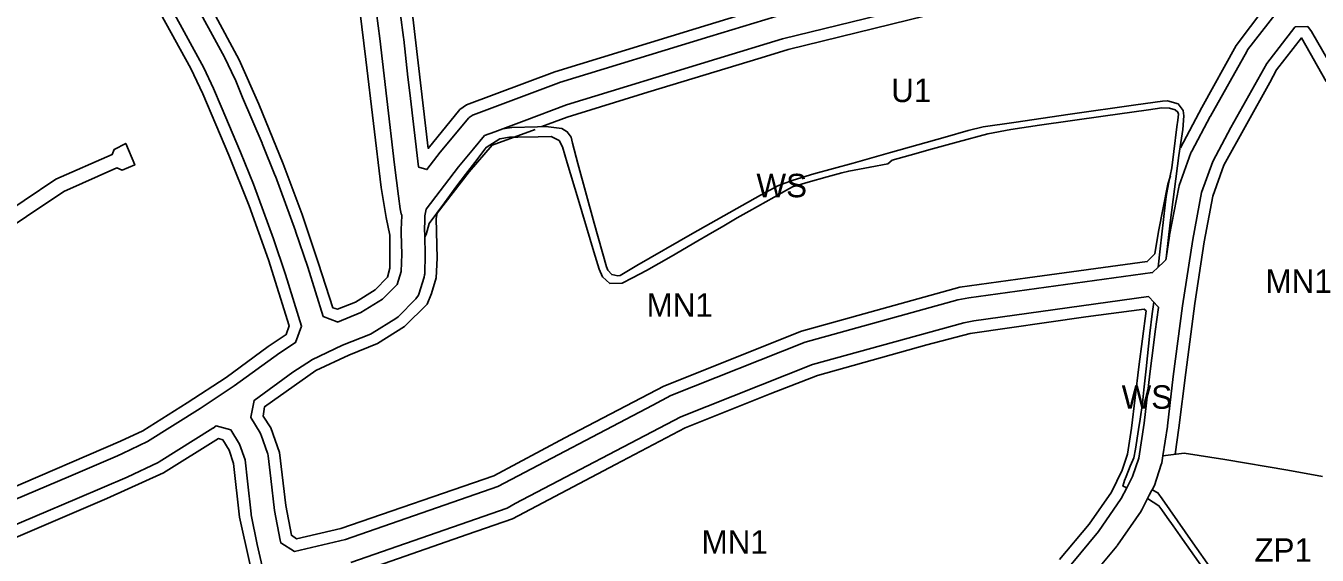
# Model space of a CAD drawing. Extents: x -284239 to -281592, y 34477 to 37267.
# Drawn here: x -283094 to -282544, y 35090 to 35315 of the extents above; entities that cross this region are included whole.
import ezdxf

# ---------------------------------------------------------------- set-up
doc = ezdxf.new("R2010")
doc.units = 0
for name, color, linetype in [('linie_rozgraniczajace', 7, 'Continuous'), ('linie_zabudowy_nieprzekraczalne', 7, 'Continuous'), ('oznaczenia_przeznaczen', 7, 'Continuous')]:
    doc.layers.add(name, color=color, linetype=linetype)

msp = doc.modelspace()

# ---------------------------------------------------------------- linework, layer by layer
at = {"layer": 'linie_rozgraniczajace'}
for points in [[(-283023.658, 35328.372), (-283009.305, 35301.979), (-283009.197, 35301.753), (-283009.173, 35301.719), (-283004.94, 35292.724), (-283004.917, 35292.623), (-283004.852, 35292.526), (-283001.616, 35284.8), (-282993.288, 35265.235), (-282993.278, 35265.188), (-282993.252, 35265.149), (-282987.696, 35251.39), (-282987.679, 35251.301), (-282987.636, 35251.234), (-282979.103, 35227.885), (-282979.09, 35227.81), (-282979.06, 35227.762), (-282973.899, 35212.407), (-282973.872, 35212.328), (-282967.245, 35191.382), (-282961.276, 35188.995), (-282961.263, 35188.954), (-282951.282, 35192.968), (-282942.065, 35198.699), (-282935.719, 35205.045), (-282934.007, 35210.499), (-282933.779, 35217.954), (-282934.057, 35226.861), (-282934.112, 35228.637), (-282933.97, 35231.156), (-282933.777, 35234.578), (-282934.115, 35235.158), (-282934.443, 35237.237), (-282935.209, 35242.6), (-282936.851, 35256.062), (-282940.134, 35284.188), (-282943.089, 35309.907), (-282946.701, 35337.049)], [(-282946.701, 35337.049), (-282943.089, 35309.907), (-282940.134, 35284.188), (-282936.851, 35256.062), (-282935.209, 35242.6), (-282934.443, 35237.237), (-282934.115, 35235.158), (-282933.777, 35234.578), (-282933.97, 35231.156), (-282934.112, 35228.637), (-282934.057, 35226.861), (-282933.779, 35217.954), (-282934.007, 35210.499), (-282935.719, 35205.045), (-282942.065, 35198.699), (-282951.282, 35192.968), (-282961.263, 35188.954), (-282961.276, 35188.995), (-282967.245, 35191.382), (-282973.872, 35212.328), (-282973.899, 35212.407), (-282979.06, 35227.762), (-282979.09, 35227.81), (-282979.103, 35227.885), (-282987.636, 35251.234), (-282987.679, 35251.301), (-282987.696, 35251.39), (-282993.252, 35265.149), (-282993.278, 35265.188), (-282993.288, 35265.235), (-283001.616, 35284.8), (-283004.852, 35292.526), (-283004.917, 35292.623), (-283004.94, 35292.724), (-283009.173, 35301.719), (-283009.197, 35301.753), (-283009.305, 35301.979), (-283023.658, 35328.372)], [(-282694.667, 35328.625), (-282771.562, 35309.736), (-282799.549, 35301.163), (-282863.566, 35281.553), (-282881.651, 35274.78), (-282890.74, 35271.377), (-282894.135, 35270.105), (-282898.529, 35268.46), (-282903.235, 35262.813), (-282909.578, 35255.201), (-282923.4, 35237.093), (-282923.928, 35234.259), (-282923.942, 35233.856), (-282923.996, 35232.362), (-282924.021, 35231.655), (-282924.117, 35228.949), (-282924.005, 35225.338), (-282923.999, 35225.17), (-282923.779, 35218.112), (-282923.807, 35217.958), (-282923.779, 35217.803), (-282924.033, 35209.505), (-282924.106, 35209.163), (-282924.26, 35208.161), (-282926.546, 35200.879), (-282926.697, 35200.464), (-282927.781, 35198.841), (-282935.401, 35191.221), (-282936.296, 35190.511), (-282946.371, 35184.246), (-282947.135, 35183.86), (-282959.042, 35179.069), (-282972.154, 35172.797), (-282972.206, 35172.77), (-282972.25, 35172.734), (-282980.259, 35167.562), (-282996.763, 35155.536), (-282998.093, 35148.443), (-282998.167, 35148.266), (-282994.172, 35141.677), (-282993.829, 35140.998), (-282993.802, 35140.862), (-282993.737, 35140.76), (-282990.995, 35133.051), (-282990.936, 35132.711), (-282990.74, 35131.953), (-282989.61, 35122.243), (-282989.608, 35122.213), (-282988.114, 35108.525), (-282985.61, 35096.001), (-282985.602, 35095.928), (-282985.585, 35095.867), (-282985.352, 35094.79), (-282979.54, 35091.157), (-282957.716, 35096.262), (-282892.893, 35118.884), (-282826.879, 35153.545), (-282819.074, 35157.58), (-282761.924, 35180.334), (-282696.836, 35198.392), (-282692.074, 35199.318), (-282613.838, 35210.056), (-282611.493, 35212.337), (-282609.231, 35214.536), (-282608.197, 35215.542), (-282608.095, 35216.198), (-282606.594, 35225.797), (-282606.576, 35225.864), (-282606.567, 35225.956), (-282602.687, 35246.429), (-282602.508, 35247.029), (-282602.481, 35247.188), (-282597.467, 35261.155), (-282597.406, 35261.251), (-282597.38, 35261.379), (-282597.171, 35261.821), (-282589.225, 35276.694), (-282589.186, 35276.769), (-282573.726, 35304.405), (-282573.512, 35304.688), (-282573.319, 35305.021), (-282561.18, 35320.73)], [(-282935.563, 35329.754), (-282933.055, 35310.346), (-282932.95, 35309.401), (-282931.166, 35293.439), (-282930.409, 35286.666), (-282926.654, 35255.132), (-282926.573, 35254.982), (-282923.107, 35253.958), (-282917.462, 35261.353), (-282917.358, 35261.472), (-282917.329, 35261.52), (-282905.363, 35275.879), (-282905.058, 35276.214), (-282903.435, 35277.297), (-282903.346, 35277.315), (-282903.276, 35277.36), (-282866.93, 35290.971), (-282866.899, 35290.977), (-282866.641, 35291.07), (-282802.477, 35310.724), (-282774.356, 35319.339)], [(-282774.356, 35319.339), (-282802.477, 35310.724), (-282866.641, 35291.07), (-282866.899, 35290.977), (-282866.93, 35290.971), (-282903.276, 35277.36), (-282903.346, 35277.315), (-282903.435, 35277.297), (-282905.058, 35276.214), (-282905.363, 35275.879), (-282917.329, 35261.52), (-282917.358, 35261.472), (-282917.462, 35261.353), (-282923.107, 35253.958), (-282926.573, 35254.982), (-282926.654, 35255.132), (-282930.409, 35286.666), (-282931.166, 35293.439), (-282932.95, 35309.401), (-282933.055, 35310.346), (-282935.563, 35329.754)], [(-282561.18, 35320.73), (-282573.319, 35305.021), (-282573.512, 35304.688), (-282573.726, 35304.405), (-282589.186, 35276.769), (-282589.225, 35276.694), (-282597.171, 35261.821), (-282597.38, 35261.379), (-282597.406, 35261.251), (-282597.467, 35261.155), (-282602.481, 35247.188), (-282602.508, 35247.029), (-282602.687, 35246.429), (-282606.567, 35225.956), (-282606.576, 35225.864), (-282606.594, 35225.797), (-282608.095, 35216.198), (-282606.314, 35231.254), (-282602.652, 35260.056), (-282600.969, 35271.042), (-282600.474, 35276.981), (-282600.771, 35279.258), (-282602.949, 35282.029), (-282607.502, 35283.316), (-282609.58, 35283.118), (-282620.963, 35281.633), (-282648.973, 35277.674), (-282673.024, 35274.111), (-282685.99, 35272.23), (-282692.424, 35270.647), (-282702.222, 35267.875), (-282725.581, 35261.343), (-282741.417, 35256.79), (-282758.243, 35252.237), (-282767.052, 35249.466), (-282773.189, 35247.189), (-282780.909, 35243.131), (-282809.909, 35226.701), (-282833.565, 35213.042), (-282840.691, 35208.786), (-282841.78, 35208.687), (-282844.353, 35209.182), (-282846.036, 35211.161), (-282846.531, 35212.547), (-282851.875, 35231.155), (-282858.804, 35256.592), (-282861.08, 35265.203), (-282861.575, 35267.875), (-282863.258, 35270.152), (-282865.633, 35271.537), (-282872.364, 35272.329), (-282876.026, 35272.23), (-282886.913, 35271.933), (-282890.74, 35271.377), (-282881.651, 35274.78), (-282863.566, 35281.553), (-282799.549, 35301.163), (-282771.562, 35309.736), (-282694.667, 35328.625)], [(-283112.522, 35107.515), (-283075.89, 35122.924), (-283054.998, 35131.962), (-283052.874, 35132.963), (-283042.222, 35137.979), (-283019.712, 35152.137), (-283005.291, 35161.695), (-282985.803, 35175.885), (-282979.105, 35180.211), (-282976.471, 35187.274), (-282983.394, 35209.273), (-282988.518, 35224.513), (-282997, 35247.723), (-283002.507, 35261.361), (-283010.83, 35280.914), (-283014.034, 35288.563), (-283018.159, 35297.33), (-283032.338, 35323.4)], [(-283032.338, 35323.4), (-283018.159, 35297.33), (-283014.034, 35288.563), (-283010.83, 35280.914), (-283002.507, 35261.361), (-282997, 35247.723), (-282988.518, 35224.513), (-282983.394, 35209.273), (-282976.471, 35187.274), (-282979.105, 35180.211), (-282985.803, 35175.885), (-283005.291, 35161.695), (-283019.712, 35152.137), (-283042.222, 35137.979), (-283052.874, 35132.963), (-283054.998, 35131.962), (-283075.89, 35122.924), (-283112.522, 35107.515)], [(-282537.013, 35297.146), (-282546.171, 35312.91), (-282547.725, 35315.01), (-282553.104, 35314.833), (-282553.156, 35314.763), (-282553.208, 35314.701), (-282553.23, 35314.664), (-282565.18, 35299.2), (-282580.435, 35271.929), (-282588.178, 35257.432), (-282592.935, 35244.18), (-282596.727, 35224.173), (-282601.146, 35195.903), (-282605.095, 35165.691), (-282607.429, 35144.68), (-282607.449, 35144.605), (-282607.462, 35144.44), (-282609.48, 35131.862), (-282609.945, 35128.969), (-282610.093, 35128.446), (-282610.133, 35128.196), (-282613.08, 35119.3), (-282614.042, 35117.421), (-282614.271, 35116.975), (-282615.248, 35115.07), (-282615.946, 35113.707), (-282616.108, 35113.39), (-282618.41, 35108.899), (-282618.53, 35108.734), (-282618.744, 35108.341), (-282628.82, 35093.777), (-282629.01, 35093.549), (-282629.078, 35093.436), (-282637.614, 35083.111)], [(-282541.458, 35123.137), (-282556.202, 35125.799), (-282582.987, 35130.277), (-282600.308, 35133.065), (-282609.48, 35131.862), (-282607.462, 35144.44), (-282607.449, 35144.605), (-282607.429, 35144.68), (-282605.095, 35165.691), (-282601.146, 35195.903), (-282596.727, 35224.173), (-282592.935, 35244.18), (-282588.178, 35257.432), (-282580.435, 35271.929), (-282565.18, 35299.2), (-282553.23, 35314.664), (-282553.208, 35314.701), (-282553.156, 35314.763), (-282553.104, 35314.833), (-282547.725, 35315.01), (-282546.171, 35312.91), (-282537.013, 35297.146)], [(-282924.117, 35228.949), (-282924.021, 35231.655), (-282923.996, 35232.362), (-282923.942, 35233.856), (-282923.928, 35234.259), (-282923.4, 35237.093), (-282909.578, 35255.201), (-282903.235, 35262.813), (-282898.529, 35268.46), (-282894.135, 35270.105), (-282890.74, 35271.377), (-282886.913, 35271.933), (-282876.026, 35272.23), (-282872.364, 35272.329), (-282865.633, 35271.537), (-282863.258, 35270.152), (-282861.575, 35267.875), (-282861.08, 35265.203), (-282858.804, 35256.592), (-282851.875, 35231.155), (-282846.531, 35212.547), (-282846.036, 35211.161), (-282844.353, 35209.182), (-282841.78, 35208.687), (-282840.691, 35208.786), (-282833.565, 35213.042), (-282809.909, 35226.701), (-282780.909, 35243.131), (-282773.189, 35247.189), (-282767.052, 35249.466), (-282758.243, 35252.237), (-282741.417, 35256.79), (-282725.581, 35261.343), (-282702.222, 35267.875), (-282692.424, 35270.647), (-282685.99, 35272.23), (-282673.024, 35274.111), (-282648.973, 35277.674), (-282620.963, 35281.633), (-282609.58, 35283.118), (-282607.502, 35283.316), (-282602.949, 35282.029), (-282600.771, 35279.258), (-282600.474, 35276.981), (-282600.969, 35271.042), (-282602.652, 35260.056), (-282606.314, 35231.254), (-282608.095, 35216.198), (-282608.197, 35215.542), (-282609.231, 35214.536), (-282611.493, 35212.337), (-282610.599, 35220.236), (-282608.483, 35238.944), (-282608.08, 35242.51), (-282606.99, 35247.844), (-282605.58, 35254.74), (-282604.732, 35261.764), (-282603.473, 35272.193), (-282603.118, 35275.128), (-282602.82, 35277.6), (-282603.12, 35278.49), (-282604.24, 35279.47), (-282606.68, 35280.19), (-282609.92, 35280.28), (-282615.628, 35279.48), (-282634.855, 35276.784), (-282662.073, 35272.967), (-282674.273, 35271.038), (-282684.05, 35269.26), (-282696.687, 35265.861), (-282707.67, 35262.79), (-282717.19, 35260.11), (-282724.87, 35258), (-282726.63, 35256.45), (-282734.19, 35255.04), (-282743.3, 35253.34), (-282746.245, 35252.571), (-282752.45, 35250.95), (-282760.58, 35248.58), (-282767.32, 35246.57), (-282769.817, 35245.174), (-282775.145, 35242.195), (-282785.787, 35236.245), (-282790.84, 35233.42), (-282796.599, 35230.047), (-282803.161, 35226.203), (-282807.64, 35223.58), (-282818.933, 35216.912), (-282829.539, 35210.992), (-282835.468, 35207.844), (-282839.92, 35205.48), (-282845.12, 35205.37), (-282848.24, 35208.28), (-282849.73, 35211.48), (-282851.937, 35218.86), (-282858.667, 35241.367), (-282863.298, 35256.857), (-282865.35, 35263.72), (-282866.73, 35266.42), (-282870.09, 35268.05)], [(-282998.167, 35148.266), (-282998.093, 35148.443), (-282996.763, 35155.536), (-282980.259, 35167.562), (-282972.25, 35172.734), (-282972.206, 35172.77), (-282972.154, 35172.797), (-282959.042, 35179.069), (-282947.135, 35183.86), (-282946.371, 35184.246), (-282936.296, 35190.511), (-282935.401, 35191.221), (-282927.781, 35198.841), (-282926.697, 35200.464), (-282926.546, 35200.879), (-282924.26, 35208.161), (-282924.106, 35209.163), (-282924.033, 35209.505), (-282923.779, 35217.803), (-282923.807, 35217.958), (-282923.779, 35218.112), (-282923.999, 35225.17), (-282924.005, 35225.338), (-282923.47, 35226.27), (-282922.12, 35231.05), (-282915.647, 35239.799), (-282910.32, 35247), (-282906.628, 35251.852), (-282902.694, 35257.023), (-282898.23, 35262.89), (-282897.87, 35263.47), (-282891.99, 35267.17), (-282887.87, 35267.78), (-282884.366, 35267.833), (-282875.676, 35267.965), (-282870.09, 35268.05), (-282866.73, 35266.42), (-282865.35, 35263.72), (-282863.298, 35256.857), (-282858.667, 35241.367), (-282851.937, 35218.86), (-282849.73, 35211.48), (-282848.24, 35208.28), (-282845.12, 35205.37), (-282839.92, 35205.48), (-282835.468, 35207.844), (-282829.539, 35210.992), (-282818.933, 35216.912), (-282807.64, 35223.58), (-282803.161, 35226.203), (-282796.599, 35230.047), (-282790.84, 35233.42), (-282785.787, 35236.245), (-282775.145, 35242.195), (-282769.817, 35245.174), (-282767.32, 35246.57), (-282760.58, 35248.58), (-282752.45, 35250.95), (-282746.245, 35252.571), (-282743.3, 35253.34), (-282734.19, 35255.04), (-282726.63, 35256.45), (-282724.87, 35258), (-282717.19, 35260.11), (-282707.67, 35262.79), (-282696.687, 35265.861), (-282684.05, 35269.26), (-282674.273, 35271.038), (-282662.073, 35272.967), (-282634.855, 35276.784), (-282615.628, 35279.48), (-282609.92, 35280.28), (-282606.68, 35280.19), (-282604.24, 35279.47), (-282603.12, 35278.49), (-282602.82, 35277.6), (-282603.118, 35275.128), (-282603.473, 35272.193), (-282604.732, 35261.764), (-282605.58, 35254.74), (-282606.99, 35247.844), (-282608.08, 35242.51), (-282608.483, 35238.944), (-282610.599, 35220.236), (-282611.493, 35212.337), (-282613.838, 35210.056), (-282692.074, 35199.318), (-282696.836, 35198.392), (-282761.924, 35180.334), (-282819.074, 35157.58), (-282826.879, 35153.545), (-282892.893, 35118.884), (-282957.716, 35096.262), (-282979.54, 35091.157), (-282985.352, 35094.79), (-282985.585, 35095.867), (-282985.602, 35095.928), (-282985.61, 35096.001), (-282988.114, 35108.525), (-282989.608, 35122.213)], [(-282870.09, 35268.05), (-282875.676, 35267.965), (-282884.366, 35267.833), (-282887.87, 35267.78), (-282891.99, 35267.17), (-282897.87, 35263.47), (-282898.23, 35262.89), (-282902.694, 35257.023), (-282906.628, 35251.852), (-282910.32, 35247), (-282915.647, 35239.799), (-282922.12, 35231.05), (-282923.47, 35226.27), (-282924.005, 35225.338), (-282924.117, 35228.949)], [(-283141.198, 35202.325), (-283077.863, 35244.694), (-283055.241, 35254.682), (-283052.992, 35253.756), (-283047.568, 35256.005), (-283051.404, 35265.133), (-283056.431, 35262.619), (-283057.225, 35260.37), (-283081.17, 35249.919), (-283148.903, 35204.411)], [(-283148.903, 35204.411), (-283081.17, 35249.919), (-283057.225, 35260.37), (-283056.431, 35262.619), (-283051.404, 35265.133), (-283047.568, 35256.005), (-283052.992, 35253.756), (-283055.241, 35254.682), (-283077.863, 35244.694), (-283141.198, 35202.325)], [(-282648.507, 35085.628), (-282636.922, 35099.643), (-282627.153, 35113.763), (-282624.836, 35118.27), (-282622.325, 35123.152), (-282619.755, 35130.948), (-282617.354, 35145.905), (-282615.028, 35166.843), (-282615.021, 35166.871), (-282615.016, 35166.939), (-282613.282, 35180.21), (-282612.662, 35184.951), (-282611.319, 35195.229), (-282611.311, 35195.288), (-282611.839, 35195.845), (-282613.331, 35197.422), (-282615.476, 35199.688), (-282615.596, 35199.802), (-282689.957, 35189.528), (-282694.323, 35188.668), (-282758.749, 35170.809), (-282814.841, 35148.518), (-282885.484, 35111.542), (-282888.924, 35109.624), (-282955.467, 35086.473)], [(-282955.467, 35086.473), (-282888.924, 35109.624), (-282885.484, 35111.542), (-282814.841, 35148.518), (-282758.749, 35170.809), (-282694.323, 35188.668), (-282689.957, 35189.528), (-282615.596, 35199.802), (-282615.476, 35199.688), (-282613.331, 35197.422), (-282613.989, 35192.519), (-282614.955, 35184.164), (-282616.587, 35169.042), (-282617.563, 35159.995), (-282618.17, 35154.374), (-282619.106, 35147.599), (-282619.811, 35143.11), (-282621.12, 35134.77), (-282621.87, 35131.1), (-282622.307, 35130.031), (-282623.353, 35127.474), (-282625.132, 35123.125), (-282625.87, 35121.32), (-282626.133, 35120.331), (-282626.51, 35118.91), (-282625.335, 35118.566), (-282625.391, 35118.442), (-282624.836, 35118.27), (-282627.153, 35113.763), (-282636.922, 35099.643), (-282648.507, 35085.628)], [(-282984.261, 35031.801), (-282984.727, 35033.927), (-282986.536, 35043.847), (-282986.543, 35043.898), (-282989.562, 35068.789), (-282995.429, 35094.107), (-282997.964, 35106.782), (-282997.992, 35107.066), (-282998.031, 35107.22), (-282999.546, 35121.106), (-283000.607, 35130.234), (-283002.988, 35136.929), (-283006.698, 35143.047), (-283012.879, 35144.669), (-283014.237, 35143.768), (-283014.294, 35143.738), (-283014.337, 35143.704), (-283037.155, 35129.353), (-283037.6, 35129.123), (-283037.687, 35129.062), (-283050.882, 35122.865), (-283072.146, 35113.651), (-283108.433, 35098.389)], [(-283108.433, 35098.389), (-283072.146, 35113.651), (-283050.882, 35122.865), (-283037.687, 35129.062), (-283037.6, 35129.123), (-283037.155, 35129.353), (-283014.337, 35143.704), (-283014.294, 35143.738), (-283014.237, 35143.768), (-283012.879, 35144.669), (-283006.698, 35143.047), (-283002.988, 35136.929), (-283000.607, 35130.234), (-282999.546, 35121.106), (-282998.031, 35107.22), (-282997.992, 35107.066), (-282997.964, 35106.782), (-282995.429, 35094.107), (-282989.562, 35068.789)], [(-282989.608, 35122.213), (-282989.61, 35122.243), (-282990.74, 35131.953), (-282990.936, 35132.711), (-282990.995, 35133.051), (-282993.737, 35140.76), (-282993.802, 35140.862), (-282993.829, 35140.998), (-282994.172, 35141.677), (-282998.167, 35148.266)], [(-282538.772, 35041.859), (-282551.853, 35043.871), (-282552.485, 35043.919), (-282552.668, 35043.964), (-282565.789, 35045.041), (-282565.808, 35045.885), (-282567.621, 35051.609), (-282568.68, 35054.953), (-282570.111, 35056.996), (-282581.07, 35072.638), (-282596.617, 35094.828), (-282609.755, 35113.582), (-282611.572, 35116.175), (-282614.042, 35117.421), (-282613.08, 35119.3), (-282610.133, 35128.196), (-282610.093, 35128.446), (-282609.945, 35128.969), (-282609.48, 35131.862), (-282600.308, 35133.065), (-282582.987, 35130.277), (-282556.202, 35125.799), (-282541.458, 35123.137)], [(-282592.555, 35084.274), (-282601.055, 35096.293), (-282605.11, 35102.027), (-282607.623, 35105.58), (-282609.953, 35108.874), (-282611.161, 35110.582), (-282615.946, 35113.707), (-282615.248, 35115.07), (-282614.271, 35116.975), (-282614.042, 35117.421), (-282611.572, 35116.175), (-282609.755, 35113.582), (-282596.617, 35094.828), (-282581.07, 35072.638)], [(-282637.614, 35083.111), (-282629.078, 35093.436), (-282629.01, 35093.549), (-282628.82, 35093.777), (-282618.744, 35108.341), (-282618.53, 35108.734), (-282618.41, 35108.899), (-282616.108, 35113.39), (-282615.946, 35113.707), (-282611.161, 35110.582), (-282609.953, 35108.874), (-282607.623, 35105.58), (-282605.11, 35102.027), (-282601.055, 35096.293), (-282592.555, 35084.274)]]:
    msp.add_lwpolyline(points, dxfattribs=at)
msp.add_lwpolyline([(-282626.51, 35118.91), (-282626.133, 35120.331), (-282625.87, 35121.32), (-282625.132, 35123.125), (-282623.353, 35127.474), (-282622.307, 35130.031), (-282621.87, 35131.1), (-282621.12, 35134.77), (-282619.811, 35143.11), (-282619.106, 35147.599), (-282618.17, 35154.374), (-282617.563, 35159.995), (-282616.587, 35169.042), (-282614.955, 35184.164), (-282613.989, 35192.519), (-282613.331, 35197.422), (-282611.839, 35195.845), (-282611.311, 35195.288), (-282611.319, 35195.229), (-282612.662, 35184.951), (-282613.282, 35180.21), (-282615.016, 35166.939), (-282615.021, 35166.871), (-282615.028, 35166.843), (-282617.354, 35145.905), (-282619.755, 35130.948), (-282622.325, 35123.152), (-282624.836, 35118.27), (-282625.391, 35118.442), (-282625.335, 35118.566)], close=True, dxfattribs=at)
at = {"layer": 'linie_zabudowy_nieprzekraczalne'}
for points in [[(-283102.439, 35117.135), (-283053.623, 35138.169), (-283044.098, 35142.601), (-283025.313, 35154.507), (-283008.644, 35165.355), (-282990.784, 35178.584), (-282983.111, 35183.611), (-282981.789, 35187.382), (-282990.652, 35215.56), (-282998.854, 35238.512), (-283007.453, 35260.208), (-283018.566, 35286.336), (-283023.725, 35297.052), (-283036.557, 35320.533), (-283057.856, 35352.945), (-283059.841, 35355.458), (-283081.272, 35382.975)], [(-283014.2, 35321.393), (-283003.088, 35300.822), (-282994.753, 35281.904), (-282984.302, 35256.504), (-282976.232, 35234.874), (-282969.221, 35213.972), (-282963.135, 35195.054), (-282961.151, 35194.393), (-282953.478, 35197.436), (-282945.144, 35202.727), (-282939.852, 35208.085), (-282938.926, 35211.922), (-282938.926, 35226.077), (-282940.513, 35233.518), (-282942.63, 35246.35), (-282949.112, 35300.986), (-282954.139, 35341.732)], [(-282601.978, 35263.251), (-282592.85, 35280.449), (-282578.166, 35306.841), (-282565.995, 35323.113), (-282557.264, 35334.226), (-282555.941, 35335.813), (-282555.941, 35337.136), (-282560.306, 35339.65), (-282573.271, 35338.128), (-282638.094, 35330.389), (-282693.392, 35323.775), (-282710.59, 35319.607), (-282769.195, 35305.188), (-282780.705, 35301.682), (-282828.991, 35286.997), (-282863.387, 35276.282), (-282874.103, 35272.313)], [(-282931.144, 35336.141), (-282922.522, 35262.986), (-282909.028, 35279.655), (-282906.25, 35281.64), (-282868.547, 35295.729), (-282808.354, 35314.183), (-282776.207, 35323.973), (-282751.618, 35330.071)], [(-282539.801, 35291.628), (-282550.385, 35310.148), (-282560.968, 35296.522), (-282563.878, 35291.165), (-282583.458, 35255.843), (-282588.22, 35242.68), (-282591.792, 35223.233), (-282595.893, 35196.84), (-282599.729, 35167.472), (-282602.64, 35143.791), (-282604.227, 35132.547)], [(-282877.013, 35271.122), (-282895.27, 35264.375), (-282905.059, 35252.998), (-282918.685, 35235.404), (-282919.082, 35233.155), (-282918.685, 35216.155), (-282919.214, 35207.821), (-282921.067, 35201.206), (-282923.051, 35196.576), (-282932.576, 35187.051), (-282944.085, 35179.775), (-282956.388, 35174.814), (-282970.411, 35168.332), (-282992.24, 35152.853), (-282992.901, 35148.885), (-282989.594, 35143.858), (-282985.89, 35133.34), (-282983.244, 35110.718), (-282980.862, 35098.018), (-282978.614, 35096.563), (-282959.828, 35100.863), (-282894.608, 35123.418), (-282864.313, 35139.624), (-282822.112, 35161.651), (-282763.507, 35185.133), (-282718.924, 35197.502), (-282695.906, 35203.852), (-282667.198, 35207.755), (-282616.134, 35214.766), (-282612.826, 35218.073), (-282611.371, 35227.598), (-282607.402, 35247.839), (-282606.212, 35251.279), (-282606.212, 35251.279)], [(-282653.44, 35087.633), (-282640.872, 35102.781), (-282631.347, 35116.407), (-282626.849, 35125.8), (-282624.468, 35132.679), (-282622.748, 35143.725), (-282619.706, 35169.919), (-282616.531, 35193.732), (-282617.457, 35194.393), (-282642.327, 35191.152), (-282691.54, 35184.14), (-282710.061, 35179.179), (-282756.628, 35166.215), (-282776.736, 35158.343), (-282812.984, 35143.791), (-282842.75, 35128.247), (-282886.671, 35105.096), (-282905.985, 35098.415), (-282953.081, 35081.879)], [(-283040.526, 34907.716), (-283020.153, 34920.284), (-282999.648, 34936.887), (-282984.038, 34950.116), (-282982.847, 34961.493), (-282981.789, 34966.322), (-282979.01, 34970.687), (-282973.851, 34977.963), (-282971.867, 34982.197), (-282970.676, 34986.033), (-282971.999, 34990.531), (-282975.571, 34997.41), (-282979.804, 35007.663), (-282989.065, 35030.153), (-282991.314, 35042.72), (-282994.489, 35067.525), (-283002.955, 35105.691), (-283005.469, 35128.578), (-283007.321, 35134.266), (-283010.099, 35138.764), (-283011.951, 35139.293), (-283035.367, 35124.609), (-283059.444, 35113.695), (-283106.408, 35093.719)]]:
    msp.add_lwpolyline(points, dxfattribs=at)

# ---------------------------------------------------------------- texts
at = {"layer": 'oznaczenia_przeznaczen'}
for s, p in [('U1', (-282725.231, 35282.774)), ('WS', (-282782.643, 35242.189)), ('MN1', (-282565.686, 35201.382)), ('MN1', (-282829.467, 35191.234)), ('WS', (-282627.008, 35151.986)), ('MN1', (-282806.034, 35090.15)), ('ZP1', (-282570.436, 35086.737))]:
    msp.add_text(s, height=10, dxfattribs=at).set_placement(p)

doc.saveas('drawing.dxf')
